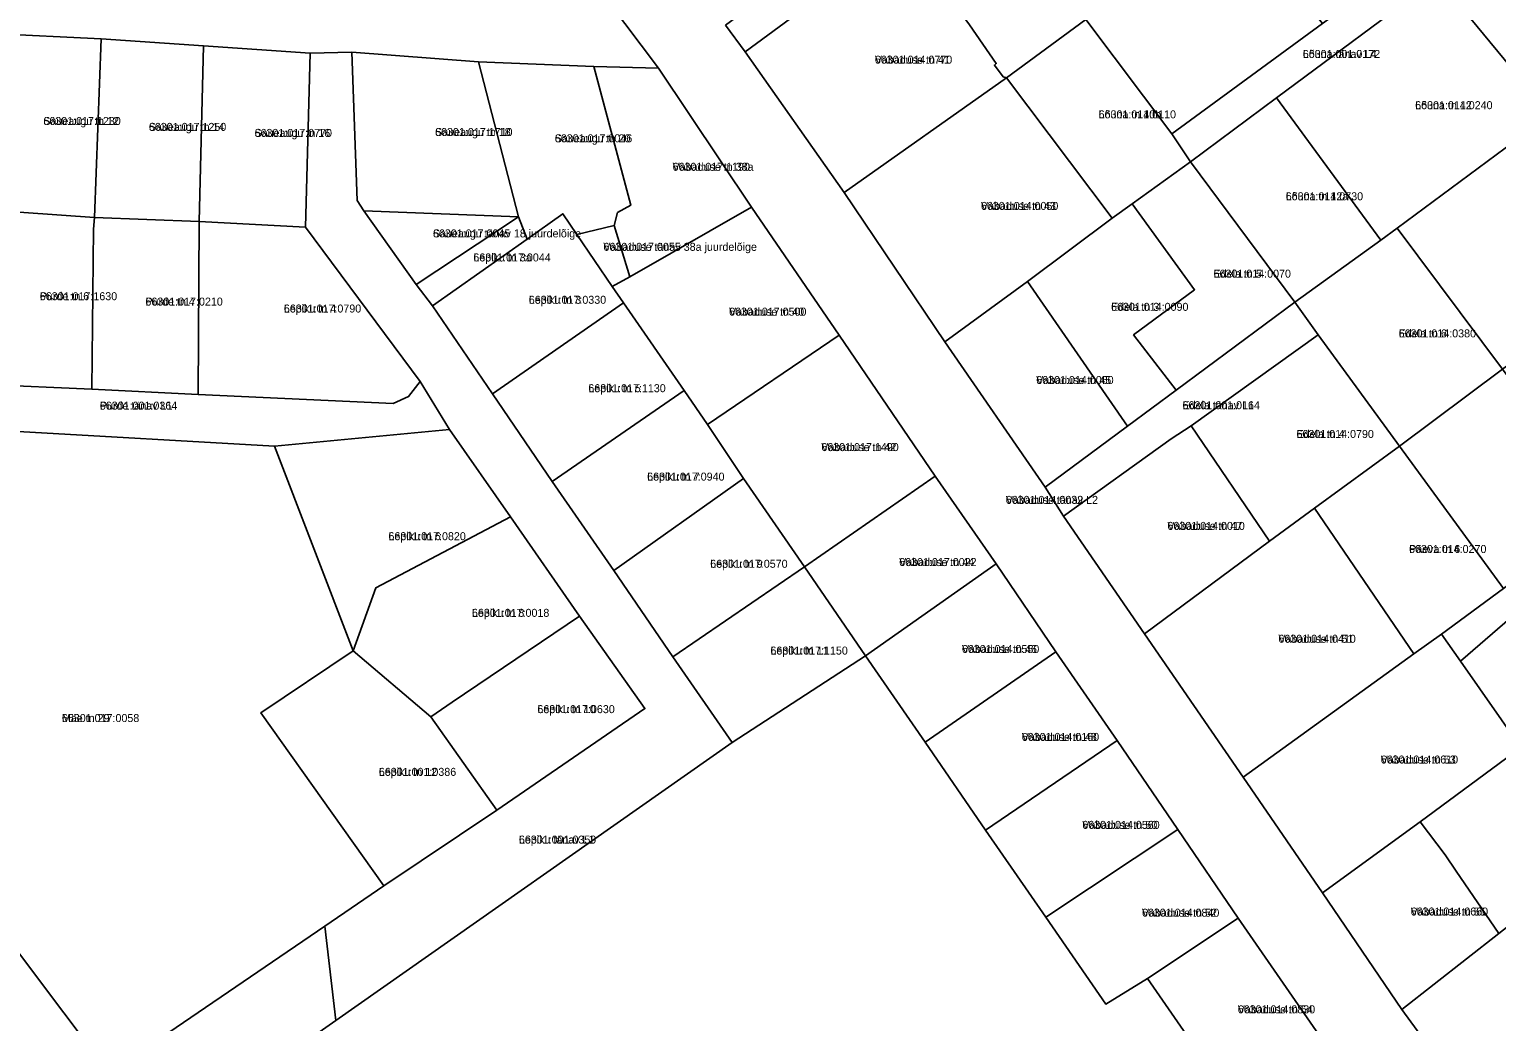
# Model space of a CAD drawing. Extents: x 632278 to 636344, y 6578401 to 6583362.
# Drawn here: x 634783.1 to 635058, y 6579911.1 to 6580097.2 of the extents above; entities that cross this region are included whole.
import ezdxf

# ---------------------------------------------------------------- set-up
doc = ezdxf.new("R2010")
doc.units = 0
for name, color, linetype in [('L_AADRESS', 7, 'Continuous'), ('PIIR', 7, 'Continuous'), ('TUNNUS', 7, 'Continuous')]:
    doc.layers.add(name, color=color, linetype=linetype)

msp = doc.modelspace()

# ---------------------------------------------------------------- linework, layer by layer
at = {"layer": 'PIIR'}
for points in [[(635068.03, 6580081.19), (635046.9, 6580106.78), (635043.18, 6580111.31), (635026.1, 6580132.11), (635006.29, 6580156.38), (635000.68, 6580163), (634983.91, 6580183.49), (634966.54, 6580204.47), (634963.06, 6580208.7), (634949.83, 6580224.87), (634928.2, 6580251.55), (634936.03, 6580257.79), (634965.26, 6580222.25), (634969.72, 6580216.83), (634985.66, 6580197.61), (635003.41, 6580176.02), (635005.89, 6580172.93), (635022.43, 6580153.24), (635026.25, 6580148.36), (635046.69, 6580123.48), (635061.31, 6580105.62)], [(634765.46, 6580108.24), (634785.89, 6580107.22), (634821.45, 6580105.69), (634865.4, 6580103.5), (634881.85, 6580115.33), (634900.95, 6580089.9), (634888.82, 6580090.2), (634867.24, 6580091.13), (634843.46, 6580092.89), (634835.67, 6580092.73), (634815.66, 6580094.1), (634796.5, 6580095.39), (634775.92, 6580096.43)], [(635026.43, 6579906.15), (635009.57, 6579930.54), (634998.25, 6579947.18), (634986.91, 6579963.84), (634975.43, 6579980.47), (634964.25, 6579996.98), (634952.8, 6580013.41), (634934.81, 6580039.85), (634918.35, 6580063.87), (634900.95, 6580089.9), (634881.85, 6580115.33)], [(634913.51, 6580097.96), (634917.19, 6580092.97), (634935.73, 6580066.61), (634954.63, 6580038.58), (634973.41, 6580011.33), (634976.83, 6580005.91), (634991.99, 6579983.84), (635010.51, 6579956.94), (635025.39, 6579935.25), (635040.21, 6579913.42), (635055.5, 6579892.53)], [(634827.14, 6579901.97), (634840.49, 6579911.35), (634914.76, 6579963.46), (634939.71, 6579979.7), (634950.9, 6579963.52), (634962.2, 6579947.05), (634973.54, 6579930.7), (634984.75, 6579914.42), (634992.58, 6579919.21), (635009.44, 6579894.82)], [(634788.63, 6579895.28), (634769.15, 6579918.49), (634770.4, 6579919.25), (634752.56, 6579941.83), (634761.47, 6579947.6), (634781.03, 6579924.08), (634798.01, 6579901.48), (634838.42, 6579929.05), (634840.49, 6579911.35), (634827.14, 6579901.97)]]:
    msp.add_lwpolyline(points, dxfattribs=at)
for points in [[(634913.51, 6580097.96), (634935.45, 6580114.15), (634957.61, 6580130.35), (634979.55, 6580146.33), (634998.64, 6580160.63), (635000.68, 6580163), (635006.29, 6580156.38), (635003.68, 6580156.99), (634977.88, 6580137.32), (634961.57, 6580125.4), (634946.91, 6580114.9), (634917.19, 6580092.97)], [(634946.91, 6580114.9), (634961.57, 6580125.4), (634981.03, 6580099.01), (634966.17, 6580088.09), (634965.55, 6580088.27), (634963.89, 6580090.5), (634964.25, 6580090.77), (634959.21, 6580098.04)], [(634997.39, 6580111.2), (635008.42, 6580119.24), (635025.38, 6580098.27), (634997.15, 6580077.59), (634981.03, 6580099.01)], [(634917.19, 6580092.97), (634946.91, 6580114.9), (634959.21, 6580098.04), (634964.25, 6580090.77), (634963.89, 6580090.5), (634965.55, 6580088.27), (634966.17, 6580088.09), (634935.73, 6580066.61)], [(635046.9, 6580106.78), (635016.75, 6580084.34), (635000.67, 6580072.32), (634997.15, 6580077.59), (635025.38, 6580098.27), (635043.18, 6580111.31)], [(635036.3, 6580057.66), (635016.75, 6580084.34), (635046.9, 6580106.78), (635068.03, 6580081.19), (635039.39, 6580059.94)], [(634981.03, 6580099.01), (634997.15, 6580077.59), (635000.67, 6580072.32), (634989.73, 6580064.47), (634985.98, 6580061.77), (634966.17, 6580088.09)], [(634775.92, 6580096.43), (634796.5, 6580095.39), (634795.24, 6580061.94), (634774.87, 6580063.32)], [(634796.5, 6580095.39), (634815.66, 6580094.1), (634814.85, 6580061.13), (634795.24, 6580061.94)], [(634815.66, 6580094.1), (634835.67, 6580092.73), (634834.82, 6580060.11), (634814.85, 6580061.13)], [(634835.67, 6580092.73), (634843.46, 6580092.89), (634844.48, 6580065.07), (634845.76, 6580063.17), (634855.56, 6580049.34), (634858.59, 6580045.32), (634869.85, 6580028.85), (634881.04, 6580012.4), (634892.55, 6579995.69), (634903.66, 6579979.51), (634914.76, 6579963.46), (634840.49, 6579911.35), (634838.42, 6579929.05), (634849.45, 6579936.6), (634870.66, 6579950.76), (634898.41, 6579969.82), (634886.17, 6579987.18), (634873.2, 6580005.79), (634861.77, 6580022.17), (634856.31, 6580031.16), (634834.82, 6580060.11)], [(634867.24, 6580091.13), (634874.73, 6580062.02), (634845.76, 6580063.17), (634844.48, 6580065.07), (634843.46, 6580092.89)], [(634867.24, 6580091.13), (634888.82, 6580090.2), (634895.79, 6580064.21), (634893.28, 6580062.82), (634892.66, 6580060.43), (634885.66, 6580058.72), (634883.05, 6580062.58), (634876.31, 6580057.86), (634874.73, 6580062.02)], [(634895.79, 6580064.21), (634888.82, 6580090.2), (634900.95, 6580089.9), (634918.35, 6580063.87), (634895.58, 6580050.79), (634892.66, 6580060.43), (634893.28, 6580062.82)], [(634935.73, 6580066.61), (634966.17, 6580088.09), (634985.98, 6580061.77), (634970.12, 6580049.92), (634954.63, 6580038.58)], [(635016.75, 6580084.34), (635036.3, 6580057.66), (635020.19, 6580046.01), (635000.67, 6580072.32)], [(635039.39, 6580059.94), (635068.03, 6580081.19), (635089.09, 6580055.77), (635074.78, 6580045.3), (635071.37, 6580042.8), (635059.1, 6580033.48)], [(634989.98, 6580039.89), (635001.39, 6580048.35), (634989.73, 6580064.47), (635000.67, 6580072.32), (635020.19, 6580046.01), (634997.94, 6580029.52)], [(634905.73, 6580029.44), (634894.37, 6580045.91), (634892.26, 6580048.97), (634895.58, 6580050.79), (634918.35, 6580063.87), (634934.81, 6580039.85), (634910.12, 6580023.12)], [(634985.98, 6580061.77), (634989.73, 6580064.47), (635001.39, 6580048.35), (634989.98, 6580039.89), (634997.94, 6580029.52), (634988.83, 6580022.76), (634970.12, 6580049.92)], [(634774.87, 6580063.32), (634795.24, 6580061.94), (634795.1, 6580059.7), (634794.75, 6580029.74), (634774.77, 6580030.62)], [(634814.69, 6580028.75), (634794.75, 6580029.74), (634795.1, 6580059.7), (634795.24, 6580061.94), (634814.85, 6580061.13)], [(634814.69, 6580028.75), (634814.85, 6580061.13), (634834.82, 6580060.11), (634856.31, 6580031.16), (634854.12, 6580028.32), (634851.2, 6580027.06)], [(634845.76, 6580063.17), (634874.73, 6580062.02), (634855.56, 6580049.34)], [(634855.56, 6580049.34), (634874.73, 6580062.02), (634876.31, 6580057.86), (634858.59, 6580045.32)], [(634858.59, 6580045.32), (634876.31, 6580057.86), (634883.01, 6580062.6), (634885.66, 6580058.72), (634892.26, 6580048.97), (634894.37, 6580045.9), (634869.85, 6580028.85)], [(634885.66, 6580058.72), (634892.66, 6580060.43), (634895.58, 6580050.79), (634892.26, 6580048.97)], [(635024.59, 6580039.9), (635020.19, 6580046.01), (635036.3, 6580057.66), (635039.39, 6580059.94), (635059.1, 6580033.48), (635039.79, 6580019.06)], [(634954.63, 6580038.58), (634970.12, 6580049.92), (634988.83, 6580022.76), (634973.41, 6580011.33)], [(634869.85, 6580028.85), (634894.37, 6580045.91), (634905.73, 6580029.44), (634881.04, 6580012.4)], [(634973.41, 6580011.33), (634988.83, 6580022.76), (634997.94, 6580029.52), (635020.19, 6580046.01), (635024.59, 6580039.9), (635000.77, 6580022.83), (634997.04, 6580020.38), (634976.83, 6580005.91)], [(634916.9, 6580012.94), (634910.12, 6580023.12), (634934.81, 6580039.85), (634952.8, 6580013.41), (634928.28, 6579996.43)], [(635000.77, 6580022.83), (635024.59, 6580039.9), (635039.79, 6580019.06), (635023.9, 6580007.4), (635015.46, 6580001.23)], [(635040.21, 6579913.42), (635058.41, 6579927.65), (635099.98, 6579960.28), (635119.92, 6579976.47), (635140.84, 6579992.88), (635153.75, 6580003.31), (635172.65, 6580018.56), (635176.28, 6580020.56), (635199.28, 6580038.81), (635210.19, 6580025.54), (635212.03, 6580023.3), (635075.73, 6579916.4), (635082.67, 6579907.83), (635055.5, 6579892.53)], [(635059.1, 6580033.48), (635078.81, 6580006.94), (635059.29, 6579992.37), (635039.79, 6580019.06)], [(634732.89, 6580024.54), (634733.53, 6580032.72), (634753.7, 6580031.86), (634774.77, 6580030.62), (634794.75, 6580029.74), (634814.69, 6580028.75), (634851.2, 6580027.06), (634854.12, 6580028.32), (634856.31, 6580031.16), (634861.77, 6580022.17), (634829.01, 6580019.04)], [(634881.04, 6580012.4), (634905.73, 6580029.44), (634910.12, 6580023.12), (634916.9, 6580012.94), (634892.55, 6579995.69)], [(635047.65, 6579983.78), (635059.29, 6579992.37), (635078.81, 6580006.94), (635110.15, 6580030.08), (635114.28, 6580025.4), (635078.64, 6579999.27), (635061.83, 6579987.92), (635051.21, 6579978.7)], [(634732.89, 6580024.54), (634829.01, 6580019.04), (634843.75, 6579980.63), (634826.43, 6579969), (634849.45, 6579936.6), (634838.42, 6579929.05), (634798.01, 6579901.48), (634781.03, 6579924.08), (634761.47, 6579947.6), (634728.84, 6579986.89), (634732.38, 6580010.94)], [(634997.04, 6580020.38), (635000.77, 6580022.83), (635015.46, 6580001.23), (634991.99, 6579983.84), (634976.83, 6580005.91)], [(634829.01, 6580019.04), (634861.77, 6580022.17), (634873.2, 6580005.79), (634848, 6579992.47), (634843.75, 6579980.63)], [(635039.79, 6580019.06), (635059.29, 6579992.37), (635047.65, 6579983.78), (635042.48, 6579980.11), (635023.9, 6580007.4)], [(634928.28, 6579996.43), (634903.66, 6579979.51), (634892.55, 6579995.69), (634916.9, 6580012.94)], [(634952.8, 6580013.41), (634964.25, 6579996.98), (634939.71, 6579979.7), (634928.28, 6579996.43)], [(634991.99, 6579983.84), (635015.46, 6580001.23), (635023.9, 6580007.4), (635042.48, 6579980.11), (635010.51, 6579956.94)], [(634873.2, 6580005.79), (634886.17, 6579987.18), (634862.3, 6579971.05), (634858.3, 6579968.26), (634843.75, 6579980.63), (634848, 6579992.47)], [(635051.21, 6579978.7), (635061.83, 6579987.92), (635078.64, 6579999.27), (635089.69, 6579982.81), (635084.8, 6579978.84), (635062.56, 6579962.5)], [(634903.66, 6579979.51), (634928.28, 6579996.43), (634939.71, 6579979.7), (634914.76, 6579963.46)], [(634939.71, 6579979.7), (634964.25, 6579996.98), (634975.43, 6579980.47), (634950.9, 6579963.52)], [(634858.3, 6579968.26), (634862.3, 6579971.05), (634886.17, 6579987.18), (634898.41, 6579969.82), (634870.66, 6579950.76)], [(635010.51, 6579956.94), (635042.48, 6579980.11), (635047.65, 6579983.78), (635051.21, 6579978.7), (635062.56, 6579962.5), (635043.7, 6579948.62), (635025.39, 6579935.25)], [(634826.43, 6579969), (634843.75, 6579980.63), (634858.3, 6579968.26), (634870.66, 6579950.76), (634849.45, 6579936.6)], [(634950.9, 6579963.52), (634975.43, 6579980.47), (634986.91, 6579963.84), (634962.2, 6579947.05)], [(635050.41, 6579939.35), (635048.33, 6579942.4), (635043.7, 6579948.62), (635062.56, 6579962.5), (635084.8, 6579978.84), (635099.98, 6579960.28), (635058.41, 6579927.65)], [(634962.2, 6579947.05), (634986.91, 6579963.84), (634998.25, 6579947.18), (634973.54, 6579930.7)], [(635025.39, 6579935.25), (635043.7, 6579948.62), (635048.33, 6579942.4), (635050.41, 6579939.35), (635058.41, 6579927.65), (635040.21, 6579913.42)], [(634973.54, 6579930.7), (634998.25, 6579947.18), (635009.57, 6579930.54), (634992.58, 6579919.21), (634984.75, 6579914.42)], [(634992.58, 6579919.21), (635009.57, 6579930.54), (635026.43, 6579906.15), (635009.44, 6579894.82)]]:
    msp.add_lwpolyline(points, close=True, dxfattribs=at)

# ---------------------------------------------------------------- texts
at = {"layer": 'L_AADRESS'}
for s, p in [('Vabaduse tn 41', (634941.49, 6580090.75)), ('Lõuna tänav L4', (635021.68, 6580091.82)), ('Lõuna tn 12', (635042.74, 6580082.22)), ('Saueaugu tn 12', (634785.68, 6580079.26)), ('Lõuna tn 10b', (634983.42, 6580080.5)), ('Saueaugu tn 14', (634805.45, 6580078.15)), ('Saueaugu tn 16', (634825.26, 6580077.02)), ('Saueaugu tn 18', (634859.09, 6580077.19)), ('Saueaugu tn 20', (634881.52, 6580076.01)), ('Vabaduse tn 38a', (634903.59, 6580070.67)), ('Lõuna tn 12a', (635018.48, 6580065.14)), ('Vabaduse tn 43', (634961.37, 6580063.33)), ('Saueaugu tänav 18 juurdelõige', (634858.68, 6580058.18)), ('Vabaduse tänav 38a juurdelõige', (634890.62, 6580055.66)), ('Lepiku tn 3a', (634866.25, 6580053.67)), ('Edela tn 5', (635004.96, 6580050.63)), ('Purde tn 6', (634785.01, 6580046.4)), ('Lepiku tn 3', (634876.64, 6580045.73)), ('Purde tn 4', (634804.8, 6580045.39)), ('Lepiku tn 4', (634830.74, 6580044.09)), ('Vabaduse tn 40', (634914.17, 6580043.5)), ('Edela tn 3', (634985.75, 6580044.41)), ('Edela tn 6', (635039.64, 6580039.43)), ('Lepiku tn 5', (634887.8, 6580029.15)), ('Vabaduse tn 45', (634971.73, 6580030.68)), ('Purde tänav L1', (634796.26, 6580025.88)), ('Edela tänav L1', (634999.14, 6580025.96)), ('Edela tn 4', (635020.5, 6580020.57)), ('Vabaduse tn 42', (634931.46, 6580018.11)), ('Lepiku tn 7', (634898.82, 6580012.57)), ('Vabaduse tänav L2', (634966.02, 6580008.21)), ('Vabaduse tn 47', (634996.31, 6580003.33)), ('Lepiku tn 6', (634850.34, 6580001.4)), ('Päeva tn 6', (635041.59, 6579999)), ('Lepiku tn 9', (634910.64, 6579996.23)), ('Vabaduse tn 44', (634946.05, 6579996.55)), ('Lepiku tn 8', (634865.99, 6579987.03)), ('Lepiku tn 11', (634921.92, 6579979.95)), ('Vabaduse tn 46', (634957.8, 6579980.25)), ('Vabaduse tn 51', (635017.11, 6579982.17)), ('Lepiku tn 10', (634878.25, 6579968.97)), ('Mäe tn 29', (634789.15, 6579967.3)), ('Vabaduse tn 48', (634969.02, 6579963.76)), ('Vabaduse tn 53', (635036.28, 6579959.52)), ('Lepiku tn 12', (634848.54, 6579957.21)), ('Vabaduse tn 50', (634980.36, 6579947.27)), ('Lepiku tänav L1', (634874.79, 6579944.51)), ('Vabaduse tn 52', (634991.54, 6579930.8)), ('Vabaduse tn 55', (635041.9, 6579931.02)), ('Vabaduse tn 54', (635009.5, 6579912.68))]:
    msp.add_text(s, height=1.5, dxfattribs=at).set_placement(p)
at = {"layer": 'TUNNUS'}
for s, p in [('66301:014:0770', (634941.49, 6580090.75)), ('66301:001:0172', (635021.68, 6580091.82)), ('66301:014:0240', (635042.74, 6580082.22)), ('66301:017:1230', (634785.68, 6580079.26)), ('66301:014:0110', (634983.42, 6580080.5)), ('66301:017:1250', (634805.45, 6580078.15)), ('66301:017:0770', (634825.26, 6580077.02)), ('66301:017:1710', (634859.09, 6580077.19)), ('66301:017:0046', (634881.52, 6580076.01)), ('66301:017:1190', (634903.59, 6580070.67)), ('66301:014:0730', (635018.48, 6580065.14)), ('66301:014:0050', (634961.37, 6580063.33)), ('66301:017:0045', (634858.68, 6580058.18)), ('66301:017:0055', (634890.62, 6580055.66)), ('66301:017:0044', (634866.25, 6580053.67)), ('66301:014:0070', (635004.96, 6580050.63)), ('66301:017:1630', (634785.01, 6580046.4)), ('66301:017:0330', (634876.64, 6580045.73)), ('66301:017:0210', (634804.8, 6580045.39)), ('66301:017:0790', (634830.74, 6580044.09)), ('66301:017:0500', (634914.17, 6580043.5)), ('66301:014:0090', (634985.75, 6580044.41)), ('66301:014:0380', (635039.64, 6580039.43)), ('66301:014:0060', (634971.73, 6580030.68)), ('66301:017:1130', (634887.8, 6580029.15)), ('66301:001:0364', (634796.26, 6580025.88)), ('66301:001:0164', (634999.14, 6580025.96)), ('66301:014:0790', (635020.5, 6580020.57)), ('66301:017:1490', (634931.46, 6580018.11)), ('66301:017:0940', (634898.82, 6580012.57)), ('66301:014:0032', (634966.02, 6580008.21)), ('66301:014:0010', (634996.31, 6580003.33)), ('66301:017:0820', (634850.34, 6580001.4)), ('66301:014:0270', (635041.59, 6579999)), ('66301:017:0570', (634910.64, 6579996.23)), ('66301:017:0022', (634946.05, 6579996.55)), ('66301:017:0018', (634865.99, 6579987.03)), ('66301:017:1150', (634921.92, 6579979.95)), ('66301:014:0550', (634957.8, 6579980.25)), ('66301:014:0410', (635017.11, 6579982.17)), ('66301:017:0630', (634878.25, 6579968.97)), ('66301:017:0058', (634789.15, 6579967.3)), ('66301:014:0160', (634969.02, 6579963.76)), ('66301:014:0610', (635036.28, 6579959.52)), ('66301:001:0386', (634848.54, 6579957.21)), ('66301:014:0560', (634980.36, 6579947.27)), ('66301:001:0359', (634874.79, 6579944.51)), ('66301:014:0840', (634991.54, 6579930.8)), ('66301:014:0660', (635041.9, 6579931.02)), ('66301:014:0830', (635009.5, 6579912.68))]:
    msp.add_text(s, height=1.5, dxfattribs=at).set_placement(p)

doc.saveas('drawing.dxf')
